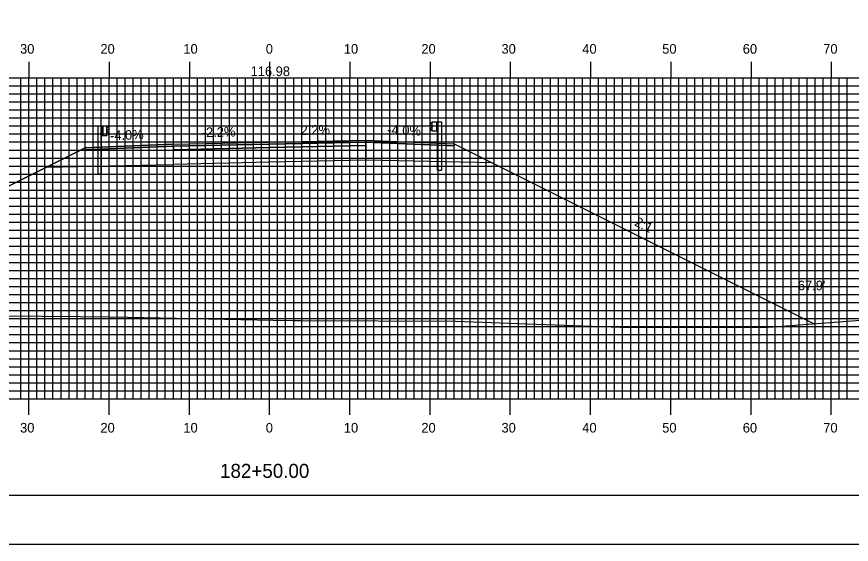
# Model space of a CAD drawing. Extents: x 1786582 to 1786926, y 442591 to 442811.
# Drawn here: x 1786716.6 to 1786820.6, y 442590.5 to 442656.3 of the extents above; entities that cross this region are included whole.
import ezdxf

# ---------------------------------------------------------------- set-up
doc = ezdxf.new("R2010")
doc.units = 0
for name, color, linetype in [('ANNOTATION', 7, 'Continuous'), ('BORDER', 7, 'Continuous'), ('D_Guardrail_Beam_Lt', 7, 'Continuous'), ('D_Guardrail_Beam_Rt', 7, 'Continuous'), ('D_Roadway_Centerline', 7, 'Continuous'), ('D_Roadway_Centerline_Text', 7, 'Continuous'), ('D_Roadway_Edge_Shoulder', 7, 'Continuous'), ('D_Roadway_Edge_TW', 7, 'Continuous'), ('D_Roadway_Pavement', 7, 'Continuous'), ('D_Roadway_SlopeLines', 7, 'Continuous'), ('D_Roadway_SubGrade', 7, 'Continuous'), ('D_Text_Standard', 7, 'Continuous'), ('H_V ANNOTATION', 7, 'Continuous'), ('MAJOR', 7, 'Continuous'), ('MINOR', 7, 'Continuous'), ('PLOT BOUNDARY', 7, 'Continuous'), ('S_Roadway_Centerline', 7, 'Continuous')]:
    doc.layers.add(name, color=color, linetype=linetype)

msp = doc.modelspace()

# ---------------------------------------------------------------- linework, layer by layer
at = {"layer": 'BORDER'}
msp.add_lwpolyline([(1786598.48, 442596.67), (1786918.48, 442596.67), (1786918.48, 442806.67), (1786598.48, 442806.67)], close=True, dxfattribs=at)
at = {"layer": 'D_Guardrail_Beam_Lt'}
for p, q in [((1786726.65, 442642.64), (1786726.65, 442636.64)), ((1786727.12, 442642.64), (1786726.65, 442642.64)), ((1786727.81, 442642.64), (1786727.12, 442642.64)), ((1786727.12, 442642.64), (1786727.12, 442641.47)), ((1786727.18, 442642.64), (1786727.18, 442641.47)), ((1786727.29, 442642.64), (1786727.29, 442641.47)), ((1786727.81, 442641.47), (1786727.81, 442642.64)), ((1786727.81, 442642.56), (1786727.88, 442642.54)), ((1786727.81, 442642.09), (1786727.81, 442642.02)), ((1786728.04, 442642.29), (1786727.85, 442642.16)), ((1786727.85, 442641.96), (1786728.04, 442641.82)), ((1786727.9, 442642.54), (1786728.04, 442642.44)), ((1786728.04, 442641.68), (1786727.9, 442641.58)), ((1786727.12, 442641.47), (1786727.81, 442641.47)), ((1786727.14, 442636.64), (1786727.14, 442641.47)), ((1786727.88, 442641.57), (1786727.81, 442641.56)), ((1786727.14, 442636.64), (1786726.65, 442636.64))]:
    msp.add_line(p, q, dxfattribs=at)
for centre, major_axis, start_param, end_param in [((1786727.89, 442642.09), (-0.0789, 0), 5.323254, 6.283185), ((1786727.89, 442642.02), (-0.0789, 0), 6.283185, 7.243116), ((1786727.87, 442642.5), (0.0417, 0), 0.959931, 1.376053), ((1786727.99, 442642.36), (0.0877, 0), 5.323254, 7.243116), ((1786727.99, 442641.75), (0.0877, 0), 5.323254, 7.243116), ((1786727.87, 442641.61), (0.0417, 0), 4.907132, 5.323254)]:
    msp.add_ellipse(centre, major_axis=major_axis, ratio=0.995501, start_param=start_param, end_param=end_param, dxfattribs=at)
at = {"layer": 'D_Guardrail_Beam_Rt'}
for p, q in [((1786768.26, 442643.06), (1786768.12, 442642.96)), ((1786768.12, 442642.82), (1786768.31, 442642.68)), ((1786768.35, 442643.08), (1786768.27, 442643.07)), ((1786768.35, 442643.17), (1786769.04, 442643.17)), ((1786768.35, 442642), (1786768.35, 442643.17)), ((1786768.87, 442643.17), (1786768.87, 442642)), ((1786768.97, 442643.17), (1786768.97, 442642)), ((1786769.04, 442643.17), (1786769.51, 442643.17)), ((1786769.04, 442643.17), (1786769.04, 442642)), ((1786769.51, 442643.17), (1786769.51, 442637.17)), ((1786768.31, 442642.49), (1786768.12, 442642.35)), ((1786768.12, 442642.21), (1786768.26, 442642.11)), ((1786768.27, 442642.1), (1786768.35, 442642.08)), ((1786768.34, 442642.62), (1786768.34, 442642.55)), ((1786769.04, 442642), (1786768.35, 442642)), ((1786769.02, 442637.17), (1786769.02, 442642)), ((1786769.02, 442637.17), (1786769.51, 442637.17))]:
    msp.add_line(p, q, dxfattribs=at)
for centre, major_axis, start_param, end_param in [((1786768.17, 442642.89), (-0.0877, 0), 5.323254, 7.243116), ((1786768.28, 442643.03), (-0.0417, 0), 4.907132, 5.323254), ((1786768.27, 442642.62), (0.0789, 0), 0, 0.959931), ((1786768.17, 442642.28), (-0.0877, 0), 5.323254, 7.243116), ((1786768.28, 442642.14), (-0.0417, 0), 0.959931, 1.376053), ((1786768.27, 442642.55), (0.0789, 0), 5.323254, 6.283185)]:
    msp.add_ellipse(centre, major_axis=major_axis, ratio=0.995501, start_param=start_param, end_param=end_param, dxfattribs=at)
at = {"layer": 'D_Roadway_Centerline'}
msp.add_lwpolyline([(1786684.52, 442619.66), (1786720.26, 442637.53), (1786725.08, 442639.94), (1786728.08, 442640.06), (1786736.08, 442640.38), (1786748.08, 442640.64), (1786760.08, 442640.9), (1786768.08, 442640.58), (1786771.08, 442640.46), (1786775.83, 442638.09), (1786815.96, 442618.02)], dxfattribs=at)
at = {"layer": 'D_Roadway_Edge_Shoulder'}
for points in [[(1786760.08, 442640.9), (1786768.08, 442640.58), (1786768.08, 442640.58), (1786771.08, 442640.46), (1786771.08, 442640.21), (1786760.08, 442640.65)], [(1786736.08, 442640.38), (1786728.08, 442640.06), (1786728.08, 442640.06), (1786725.08, 442639.94), (1786725.08, 442639.69), (1786736.08, 442640.13)]]:
    msp.add_lwpolyline(points, close=True, dxfattribs=at)
at = {"layer": 'D_Roadway_Edge_TW'}
msp.add_lwpolyline([(1786736.08, 442640.13), (1786736.08, 442640.38), (1786748.08, 442640.64), (1786760.08, 442640.9), (1786760.08, 442640.65), (1786748.08, 442640.39)], close=True, dxfattribs=at)
at = {"layer": 'D_Roadway_Pavement'}
msp.add_lwpolyline([(1786736.08, 442639.71), (1786736.08, 442640.13), (1786748.08, 442640.39), (1786760.08, 442640.65), (1786760.08, 442640.24), (1786748.08, 442639.97)], close=True, dxfattribs=at)
for points in [[(1786760.08, 442640.65), (1786760.08, 442640.24)], [(1786736.08, 442640.13), (1786736.08, 442639.71)]]:
    msp.add_lwpolyline(points, dxfattribs=at)
at = {"layer": 'D_Roadway_SlopeLines'}
for points in [[(1786725.08, 442639.94), (1786682.95, 442618.88)], [(1786771.08, 442640.46), (1786815.96, 442618.02)]]:
    msp.add_lwpolyline(points, dxfattribs=at)
at = {"layer": 'D_Roadway_SubGrade'}
for points in [[(1786736.08, 442637.88), (1786736.08, 442640.13), (1786736.08, 442639.71), (1786748.08, 442639.97), (1786760.08, 442640.24), (1786760.08, 442640.65), (1786760.08, 442638.4), (1786748.08, 442638.14)], [(1786760.08, 442640.24), (1786760.08, 442640.65), (1786771.08, 442640.21), (1786771.08, 442640.46), (1786775.83, 442638.09), (1786760.08, 442638.4)], [(1786736.08, 442639.71), (1786736.08, 442640.13), (1786725.08, 442639.69), (1786725.08, 442639.94), (1786720.26, 442637.53), (1786736.08, 442637.88)]]:
    msp.add_lwpolyline(points, close=True, dxfattribs=at)
at = {"layer": 'MAJOR'}
for p, q in [((1786718.08, 442650.67), (1786718.08, 442648.67)), ((1786728.08, 442650.67), (1786728.08, 442648.67)), ((1786738.08, 442650.67), (1786738.08, 442648.67)), ((1786748.08, 442650.67), (1786748.08, 442648.67)), ((1786758.08, 442650.67), (1786758.08, 442648.67)), ((1786768.08, 442650.67), (1786768.08, 442648.67)), ((1786778.08, 442650.67), (1786778.08, 442648.67)), ((1786788.08, 442650.67), (1786788.08, 442648.67)), ((1786798.08, 442650.67), (1786798.08, 442648.67)), ((1786808.08, 442650.67), (1786808.08, 442648.67)), ((1786818.08, 442650.67), (1786818.08, 442648.67)), ((1786608.08, 442648.67), (1786888.08, 442648.67)), ((1786608.08, 442648.67), (1786888.08, 442648.67)), ((1786718.08, 442608.67), (1786718.08, 442648.67)), ((1786728.08, 442608.67), (1786728.08, 442648.67)), ((1786738.08, 442608.67), (1786738.08, 442648.67)), ((1786748.08, 442608.67), (1786748.08, 442648.67)), ((1786758.08, 442608.67), (1786758.08, 442648.67)), ((1786768.08, 442608.67), (1786768.08, 442648.67)), ((1786778.08, 442608.67), (1786778.08, 442648.67)), ((1786788.08, 442608.67), (1786788.08, 442648.67)), ((1786798.08, 442608.67), (1786798.08, 442648.67)), ((1786808.08, 442608.67), (1786808.08, 442648.67)), ((1786818.08, 442608.67), (1786818.08, 442648.67)), ((1786608.08, 442643.67), (1786888.08, 442643.67)), ((1786608.08, 442638.67), (1786888.08, 442638.67)), ((1786608.08, 442633.67), (1786888.08, 442633.67)), ((1786608.08, 442628.67), (1786888.08, 442628.67)), ((1786608.08, 442623.67), (1786888.08, 442623.67)), ((1786608.08, 442618.67), (1786888.08, 442618.67)), ((1786608.08, 442613.67), (1786888.08, 442613.67)), ((1786608.08, 442608.67), (1786888.08, 442608.67)), ((1786608.08, 442608.67), (1786888.08, 442608.67)), ((1786718.08, 442606.66), (1786718.08, 442608.67)), ((1786728.08, 442606.66), (1786728.08, 442608.67)), ((1786738.08, 442606.66), (1786738.08, 442608.67)), ((1786748.08, 442606.66), (1786748.08, 442608.67)), ((1786758.08, 442606.66), (1786758.08, 442608.67)), ((1786768.08, 442606.66), (1786768.08, 442608.67)), ((1786778.08, 442606.66), (1786778.08, 442608.67)), ((1786788.08, 442606.66), (1786788.08, 442608.67)), ((1786798.08, 442606.66), (1786798.08, 442608.67)), ((1786808.08, 442606.66), (1786808.08, 442608.67)), ((1786818.08, 442606.66), (1786818.08, 442608.67))]:
    msp.add_line(p, q, dxfattribs=at)
at = {"layer": 'MINOR'}
for p, q in [((1786717.08, 442608.67), (1786717.08, 442648.67)), ((1786719.08, 442608.67), (1786719.08, 442648.67)), ((1786720.08, 442608.67), (1786720.08, 442648.67)), ((1786721.08, 442608.67), (1786721.08, 442648.67)), ((1786722.08, 442608.67), (1786722.08, 442648.67)), ((1786723.08, 442608.67), (1786723.08, 442648.67)), ((1786724.08, 442608.67), (1786724.08, 442648.67)), ((1786725.08, 442608.67), (1786725.08, 442648.67)), ((1786726.08, 442608.67), (1786726.08, 442648.67)), ((1786727.08, 442608.67), (1786727.08, 442648.67)), ((1786729.08, 442608.67), (1786729.08, 442648.67)), ((1786730.08, 442608.67), (1786730.08, 442648.67)), ((1786731.08, 442608.67), (1786731.08, 442648.67)), ((1786732.08, 442608.67), (1786732.08, 442648.67)), ((1786733.08, 442608.67), (1786733.08, 442648.67)), ((1786734.08, 442608.67), (1786734.08, 442648.67)), ((1786735.08, 442608.67), (1786735.08, 442648.67)), ((1786736.08, 442608.67), (1786736.08, 442648.67)), ((1786737.08, 442608.67), (1786737.08, 442648.67)), ((1786739.08, 442608.67), (1786739.08, 442648.67)), ((1786740.08, 442608.67), (1786740.08, 442648.67)), ((1786741.08, 442608.67), (1786741.08, 442648.67)), ((1786742.08, 442608.67), (1786742.08, 442648.67)), ((1786743.08, 442608.67), (1786743.08, 442648.67)), ((1786744.08, 442608.67), (1786744.08, 442648.67)), ((1786745.08, 442608.67), (1786745.08, 442648.67)), ((1786746.08, 442608.67), (1786746.08, 442648.67)), ((1786747.08, 442608.67), (1786747.08, 442648.67)), ((1786749.08, 442608.67), (1786749.08, 442648.67)), ((1786750.08, 442608.67), (1786750.08, 442648.67)), ((1786751.08, 442608.67), (1786751.08, 442648.67)), ((1786752.08, 442608.67), (1786752.08, 442648.67)), ((1786753.08, 442608.67), (1786753.08, 442648.67)), ((1786754.08, 442608.67), (1786754.08, 442648.67)), ((1786755.08, 442608.67), (1786755.08, 442648.67)), ((1786756.08, 442608.67), (1786756.08, 442648.67)), ((1786757.08, 442608.67), (1786757.08, 442648.67)), ((1786759.08, 442608.67), (1786759.08, 442648.67)), ((1786760.08, 442608.67), (1786760.08, 442648.67)), ((1786761.08, 442608.67), (1786761.08, 442648.67)), ((1786762.08, 442608.67), (1786762.08, 442648.67)), ((1786763.08, 442608.67), (1786763.08, 442648.67)), ((1786764.08, 442608.67), (1786764.08, 442648.67)), ((1786765.08, 442608.67), (1786765.08, 442648.67)), ((1786766.08, 442608.67), (1786766.08, 442648.67)), ((1786767.08, 442608.67), (1786767.08, 442648.67)), ((1786769.08, 442608.67), (1786769.08, 442648.67)), ((1786770.08, 442608.67), (1786770.08, 442648.67)), ((1786771.08, 442608.67), (1786771.08, 442648.67)), ((1786772.08, 442608.67), (1786772.08, 442648.67)), ((1786773.08, 442608.67), (1786773.08, 442648.67)), ((1786774.08, 442608.67), (1786774.08, 442648.67)), ((1786775.08, 442608.67), (1786775.08, 442648.67)), ((1786776.08, 442608.67), (1786776.08, 442648.67)), ((1786777.08, 442608.67), (1786777.08, 442648.67)), ((1786779.08, 442608.67), (1786779.08, 442648.67)), ((1786780.08, 442608.67), (1786780.08, 442648.67)), ((1786781.08, 442608.67), (1786781.08, 442648.67)), ((1786782.08, 442608.67), (1786782.08, 442648.67)), ((1786783.08, 442608.67), (1786783.08, 442648.67)), ((1786784.08, 442608.67), (1786784.08, 442648.67)), ((1786785.08, 442608.67), (1786785.08, 442648.67)), ((1786786.08, 442608.67), (1786786.08, 442648.67)), ((1786787.08, 442608.67), (1786787.08, 442648.67)), ((1786789.08, 442608.67), (1786789.08, 442648.67)), ((1786790.08, 442608.67), (1786790.08, 442648.67)), ((1786791.08, 442608.67), (1786791.08, 442648.67)), ((1786792.08, 442608.67), (1786792.08, 442648.67)), ((1786793.08, 442608.67), (1786793.08, 442648.67)), ((1786794.08, 442608.67), (1786794.08, 442648.67)), ((1786795.08, 442608.67), (1786795.08, 442648.67)), ((1786796.08, 442608.67), (1786796.08, 442648.67)), ((1786797.08, 442608.67), (1786797.08, 442648.67)), ((1786799.08, 442608.67), (1786799.08, 442648.67)), ((1786800.08, 442608.67), (1786800.08, 442648.67)), ((1786801.08, 442608.67), (1786801.08, 442648.67)), ((1786802.08, 442608.67), (1786802.08, 442648.67)), ((1786803.08, 442608.67), (1786803.08, 442648.67)), ((1786804.08, 442608.67), (1786804.08, 442648.67)), ((1786805.08, 442608.67), (1786805.08, 442648.67)), ((1786806.08, 442608.67), (1786806.08, 442648.67)), ((1786807.08, 442608.67), (1786807.08, 442648.67)), ((1786809.08, 442608.67), (1786809.08, 442648.67)), ((1786810.08, 442608.67), (1786810.08, 442648.67)), ((1786811.08, 442608.67), (1786811.08, 442648.67)), ((1786812.08, 442608.67), (1786812.08, 442648.67)), ((1786813.08, 442608.67), (1786813.08, 442648.67)), ((1786814.08, 442608.67), (1786814.08, 442648.67)), ((1786815.08, 442608.67), (1786815.08, 442648.67)), ((1786816.08, 442608.67), (1786816.08, 442648.67)), ((1786817.08, 442608.67), (1786817.08, 442648.67)), ((1786819.08, 442608.67), (1786819.08, 442648.67)), ((1786820.08, 442608.67), (1786820.08, 442648.67)), ((1786608.08, 442647.67), (1786888.08, 442647.67)), ((1786608.08, 442646.67), (1786888.08, 442646.67)), ((1786608.08, 442645.67), (1786888.08, 442645.67)), ((1786608.08, 442644.67), (1786888.08, 442644.67)), ((1786608.08, 442642.67), (1786888.08, 442642.67)), ((1786608.08, 442641.67), (1786888.08, 442641.67)), ((1786608.08, 442640.67), (1786888.08, 442640.67)), ((1786608.08, 442639.67), (1786888.08, 442639.67)), ((1786608.08, 442637.67), (1786888.08, 442637.67)), ((1786608.08, 442636.67), (1786888.08, 442636.67)), ((1786608.08, 442635.67), (1786888.08, 442635.67)), ((1786608.08, 442634.67), (1786888.08, 442634.67)), ((1786608.08, 442632.67), (1786888.08, 442632.67)), ((1786608.08, 442631.67), (1786888.08, 442631.67)), ((1786608.08, 442630.67), (1786888.08, 442630.67)), ((1786608.08, 442629.67), (1786888.08, 442629.67)), ((1786608.08, 442627.67), (1786888.08, 442627.67)), ((1786608.08, 442626.67), (1786888.08, 442626.67)), ((1786608.08, 442625.67), (1786888.08, 442625.67)), ((1786608.08, 442624.67), (1786888.08, 442624.67)), ((1786608.08, 442622.67), (1786888.08, 442622.67)), ((1786608.08, 442621.67), (1786888.08, 442621.67)), ((1786608.08, 442620.67), (1786888.08, 442620.67)), ((1786608.08, 442619.67), (1786888.08, 442619.67)), ((1786608.08, 442617.67), (1786888.08, 442617.67)), ((1786608.08, 442616.67), (1786888.08, 442616.67)), ((1786608.08, 442615.67), (1786888.08, 442615.67)), ((1786608.08, 442614.67), (1786888.08, 442614.67)), ((1786608.08, 442612.67), (1786888.08, 442612.67)), ((1786608.08, 442611.67), (1786888.08, 442611.67)), ((1786608.08, 442610.67), (1786888.08, 442610.67)), ((1786608.08, 442609.67), (1786888.08, 442609.67))]:
    msp.add_line(p, q, dxfattribs=at)
at = {"layer": 'PLOT BOUNDARY'}
msp.add_lwpolyline([(1786582.29, 442590.55), (1786922.29, 442590.55), (1786922.29, 442810.55), (1786582.29, 442810.55)], close=True, dxfattribs=at)
at = {"layer": 'S_Roadway_Centerline'}
msp.add_lwpolyline([(1786710.05, 442619.04), (1786724.45, 442618.91), (1786728, 442618.9), (1786730.42, 442618.83), (1786748.51, 442618.48), (1786751.03, 442618.43), (1786751.39, 442618.41), (1786751.88, 442618.41), (1786771.3, 442618.35), (1786779.01, 442618.07), (1786791.83, 442617.6), (1786798.59, 442617.56), (1786807.96, 442617.59), (1786810.22, 442617.61), (1786811.9, 442617.72), (1786828.25, 442618.95)], dxfattribs=at)

# ---------------------------------------------------------------- texts
at = {"layer": 'ANNOTATION'}
for s, rotation, p in [('2.2%', 1.2603, (1786751.96, 442641.53)), ('-4.0%', 357.7094, (1786762.72, 442641.62)), ('-4.0%', 2.2906, (1786728.21, 442640.86)), ('-2.2%', 1.2603, (1786739.64, 442641.26)), ('2:1', 333.4349, (1786793.45, 442630.31))]:
    msp.add_text(s, height=1.2, rotation=rotation, dxfattribs=at).set_placement(p)
at = {"layer": 'D_Roadway_Centerline'}
for s, p in [('C', (1786748.07, 442640.64)), ('L', (1786748.08, 442640.63))]:
    msp.add_text(s, height=0.0146, dxfattribs=at).set_placement(p)
at = {"layer": 'D_Roadway_Centerline_Text'}
msp.add_text('116.98', height=1.2, dxfattribs=at).set_placement((1786745.71, 442648.88))
at = {"layer": 'D_Text_Standard'}
msp.add_text("67.9'", height=1.2, dxfattribs=at).set_placement((1786813.92, 442622.2))
at = {"layer": 'H_V ANNOTATION'}
for s, height, p in [('30', 1.2, (1786716.98, 442651.67)), ('20', 1.2, (1786726.99, 442651.67)), ('10', 1.2, (1786737.33, 442651.67)), ('0', 1.2, (1786747.6, 442651.67)), ('10', 1.2, (1786757.33, 442651.67)), ('20', 1.2, (1786766.99, 442651.67)), ('30', 1.2, (1786776.98, 442651.67)), ('40', 1.2, (1786787.05, 442651.67)), ('50', 1.2, (1786797.01, 442651.67)), ('60', 1.2, (1786807.05, 442651.67)), ('70', 1.2, (1786817.08, 442651.67)), ('30', 1.2, (1786716.98, 442604.47)), ('20', 1.2, (1786726.99, 442604.47)), ('10', 1.2, (1786737.33, 442604.47)), ('0', 1.2, (1786747.6, 442604.47)), ('10', 1.2, (1786757.33, 442604.47)), ('20', 1.2, (1786766.99, 442604.47)), ('30', 1.2, (1786776.98, 442604.47)), ('40', 1.2, (1786787.05, 442604.47)), ('50', 1.2, (1786797.01, 442604.47)), ('60', 1.2, (1786807.05, 442604.47)), ('70', 1.2, (1786817.08, 442604.47)), ('182+50.00', 1.75, (1786741.9, 442598.82))]:
    msp.add_text(s, height=height, dxfattribs=at).set_placement(p)

doc.saveas('drawing.dxf')
